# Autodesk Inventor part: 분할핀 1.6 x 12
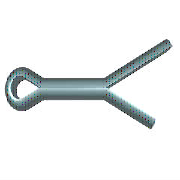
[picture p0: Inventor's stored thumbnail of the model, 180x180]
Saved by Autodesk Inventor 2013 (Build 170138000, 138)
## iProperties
IsCustomPart: 1
Created: 2012-02
Part Number: 분할핀 1.6 x 12
Material: 강철, 연강
Description: 분할 핀
Document SubType Name: Modeling
Standard: KS B 1321
Designer: mduedu
Standards Organization: KS
Language: ko-KR
Size Designation: 1.6 x  12
Categories: <MemberInstance><Categories><Category DisplayName="조임쇠" InternalName="e4da775c-781d-43d5-af7c-5136215cf5a6" Mnemonic="FSTN"><Category DisplayName="핀" InternalNa
Density: 1 g/cm^3
Author: mduedu
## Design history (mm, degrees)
sketch "스케치1"
  geometry: L1 (0, 0.7)-(7, 0.7); L2 (0, -0.7)-(7, -0.7); L3 (7, 0.7)-(12, 2.616); L4 (12, 2.616)-(12.234, 2.005); L5 (12.234, 2.005)-(7, 0); L6 (7, 0)-(14.734, -2.963); L7 (14.734, -2.963)-(14.5, -3.573); L8 (14.5, -3.573)-(7, -0.7); L9 (0, 0)-(-1.528, -0.645); L10 (0, 0)-(-1.528, 0.645); L11 (0, 0.7)-(0, -0.7); L12 (0, 0.7)-(-1.204, 1.267); L13 (0, -0.7)-(-1.204, -1.267); L14 (-3.2, 0)-(7, 0); L15 (7, 0.7)-(7, -0.7); A1 r 1.4 centre (-1.8, 0) between (-1.204, 1.267) and (-1.204, -1.267); A2 r 0.7 centre (-1.8, 0) between (-1.528, 0.645) and (-1.528, -0.645); 1 further point
  constraints: 30 end point, 5 point on circle, 4 parallel, 4 perpendicular, 4 point on line, 4 tangent, 2 centre point, 2 midpoint, 1 coincident, 1 horizontal
  dimensions: "d0" = 7 distance of L1.start L1.end (= MSIAB); "d1" = 12 horizontal distance of L1.start L3.end (= SNLG); "d2" = 159.037 deg angle of L1 L3; "d3" = 159.037 deg angle of L2 L8; "d4" = 2.5 horizontal distance of L3.end L7.end (= LGDIF); "d5" = 0.7 radius of A2 (= -0.5 x SNND1 + 0.5 x KBR); "d6" = 1.4 radius of A1 (= 0.5 x KBR); "d7" = 0.7 distance from line of L1 L9.start (= 0.5 x SNND1); "d8" = 0.7 distance between parallel lines of L2 L14 (= 0.5 x SNND1); "d9" = 1.8 distance from line of L11 A1.centre (= KOL - 0.5 x KBR)
extrude "본체" new body sketch "스케치1" stored distance "d10" = 1.4 (= SNND1); taper "d11" = 0 deg
workaxis "Work Axis1"
workplane "Work Plane1"
workplane "Work Plane3"
body "Solid1"
fillet "모깎기" dims "d12" = 0.49 (= 0.35 x SNND1)
other parameters: "SNND" = 1.6 [user parameter], "SNLG" = 12 [user parameter; used in 1 equation term], "SNND1" = 1.4 [user parameter; used in 5 equation terms], "KBR" = 2.8 [user parameter; used in 3 equation terms], "KOL" = 3.2 [user parameter; used in 1 equation term], "LGDIF" = 2.5 [user parameter; used in 1 equation term], "MSIAB" = 7 [user parameter; used in 1 equation term], "d15" = 0, "d16" = 0, "d17" = 0, "NNDMAX" = 7 [user parameter], "DSH" = 6 [user parameter], "NNDMIN" = 5.5 [user parameter]
